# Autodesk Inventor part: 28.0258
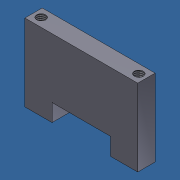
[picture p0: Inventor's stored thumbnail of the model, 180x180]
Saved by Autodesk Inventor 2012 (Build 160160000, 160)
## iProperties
Created: 2012-11
Part Number: 28.0258
Document SubType Name: Modeling
Designer: Administrator
Density: 1 g/cm^3
Material: Default
Mass: 12.6531 g
Surface Area: 51.5612 cm^2
Volume: 12.6531 cm^3
Description: NUT SLIDE CONNECTOR 35.5
Vendor: S
Translation Standard: STEP AP214IS
FileName: K:\Alle\Neum\von Trenz\28.0258 Nut slide connector 35.5.stp
PreProcessor: Autodesk Inventor 2011
PostProcessor: Build: 236a, Release: 2009 RTM - Date: Fri 02/22/2008
Sent Units: MM
Uncertainty: 0.01
Author: Administrator
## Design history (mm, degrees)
feature "Base1"
sketch "Sketch1"
  geometry: C1 r 2.067 at (48.5, 4) reference; C2 r 2.067 at (3.5, 4) reference; C3 r 2 at (3.5, 4); C4 r 2 at (48.5, 4); 1 further point
  constraints: 2 centre point, 2 coincident
  dimensions: "d0" = 4 diameter of C3; "d1" = 4 diameter of C4
extrude "Extrusion1" join sketch "Sketch1" distance "d2" = 16; taper "d3" = 0 deg
sketch "Sketch2"
  geometry: C1 r 2 at (3.5, 4) reference; C2 r 2 at (48.5, 4) reference; 3 further points
  constraints: 2 coincident
hole "Hole1" sketch "Sketch2" at (3.5, 4), (48.5, 4) diameter "d4" = 4.134; stored, may be unused: countersink angle "d8" = 90 deg, drill point angle "d10" = 118 deg; dims "d5" = 6, "d6" = 4, "d7" = 2, "d9" = 14
body "Solid1"
